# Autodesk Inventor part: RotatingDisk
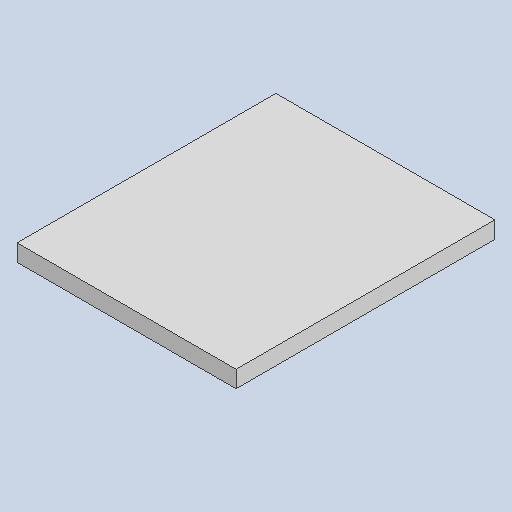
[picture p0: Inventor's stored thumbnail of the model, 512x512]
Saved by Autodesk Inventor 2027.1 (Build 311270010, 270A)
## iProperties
Created: 2026-07
Part Number: RotatingDisk
Material: Generic
Document SubType Name: Modeling
Designer: dunge
Density: 1 g/cm^3
Appearance: Default
Mass: 1.47303 g
Surface Area: 42.135 cm^2
Volume: 1.47303 cm^3
Author: dunge
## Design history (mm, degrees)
sketch "Sketch1"
  geometry: L1 (-0.381, 24.126)-(-0.381, 23.392); L2 (0.381, 24.126)-(0.381, 23.392); L3 (-2.901, 23.955)-(-2.824, 23.224); L4 (-2.143, 24.034)-(-2.066, 23.304); L5 (-5.389, 23.52)-(-5.236, 22.802); L6 (-4.644, 23.678)-(-4.491, 22.96); L7 (-7.818, 22.828)-(-7.591, 22.13); L8 (-7.093, 23.063)-(-6.866, 22.365); L9 (-10.161, 21.886)-(-9.862, 21.215); L10 (-9.465, 22.196)-(-9.166, 21.525); L11 (-12.393, 20.704)-(-12.026, 20.068); L12 (-11.733, 21.085)-(-11.366, 20.449); L13 (-14.489, 19.295)-(-14.058, 18.701); L14 (-13.873, 19.743)-(-13.441, 19.149); L15 (-16.427, 17.675)-(-15.935, 17.129); L16 (-15.861, 18.184)-(-15.369, 17.639); L17 (-18.184, 15.861)-(-17.639, 15.369); L18 (-17.675, 16.427)-(-17.129, 15.935); L19 (-19.743, 13.873)-(-19.149, 13.441); L20 (-19.295, 14.489)-(-18.701, 14.058); L21 (-21.085, 11.733)-(-20.449, 11.366); L22 (-20.704, 12.393)-(-20.068, 12.026); L23 (-22.196, 9.465)-(-21.525, 9.166); L24 (-21.886, 10.161)-(-21.215, 9.862); L25 (-23.063, 7.093)-(-22.365, 6.866); L26 (-22.828, 7.818)-(-22.13, 7.591); L27 (-23.678, 4.644)-(-22.96, 4.491); L28 (-23.52, 5.389)-(-22.802, 5.236); L29 (-24.034, 2.143)-(-23.304, 2.066); L30 (-23.955, 2.901)-(-23.224, 2.824); L31 (-24.126, -0.381)-(-23.392, -0.381); L32 (-24.126, 0.381)-(-23.392, 0.381); L33 (-23.955, -2.901)-(-23.224, -2.824); L34 (-24.034, -2.143)-(-23.304, -2.066); L35 (-23.52, -5.389)-(-22.802, -5.236); L36 (-23.678, -4.644)-(-22.96, -4.491); L37 (-22.828, -7.818)-(-22.13, -7.591); L38 (-23.063, -7.093)-(-22.365, -6.866); L39 (-21.886, -10.161)-(-21.215, -9.862); L40 (-22.196, -9.465)-(-21.525, -9.166); L41 (-20.704, -12.393)-(-20.068, -12.026); L42 (-21.085, -11.733)-(-20.449, -11.366); L43 (-19.295, -14.489)-(-18.701, -14.058); L44 (-19.743, -13.873)-(-19.149, -13.441); L45 (-17.675, -16.427)-(-17.129, -15.935); L46 (-18.184, -15.861)-(-17.639, -15.369); L47 (-15.861, -18.184)-(-15.369, -17.639); L48 (-16.427, -17.675)-(-15.935, -17.129); L49 (-13.873, -19.743)-(-13.441, -19.149); L50 (-14.489, -19.295)-(-14.058, -18.701); L51 (-11.733, -21.085)-(-11.366, -20.449); L52 (-12.393, -20.704)-(-12.026, -20.068); L53 (-9.465, -22.196)-(-9.166, -21.525); L54 (-10.161, -21.886)-(-9.862, -21.215); L55 (-7.093, -23.063)-(-6.866, -22.365); L56 (-7.818, -22.828)-(-7.591, -22.13); L57 (-4.644, -23.678)-(-4.491, -22.96); L58 (-5.389, -23.52)-(-5.236, -22.802); L59 (-2.143, -24.034)-(-2.066, -23.304); L60 (-2.901, -23.955)-(-2.824, -23.224); L61 (0.381, -24.126)-(0.381, -23.392); L62 (-0.381, -24.126)-(-0.381, -23.392); L63 (2.901, -23.955)-(2.824, -23.224); L64 (2.143, -24.034)-(2.066, -23.304)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; C1 r 25.4 at (0, 0); C2 r 2.842 at (0, 0); A1 r 0.381 centre (0, 23.392) between (-0.381, 23.392) and (0.381, 23.392); A2 r 0.381 centre (0, 24.126) between (0.381, 24.126) and (-0.381, 24.126); A3 r 0.381 centre (-2.445, 23.264) between (-2.824, 23.224) and (-2.066, 23.304); A4 r 0.381 centre (-2.522, 23.994) between (-2.143, 24.034) and (-2.901, 23.955); A5 r 0.381 centre (-4.864, 22.881) between (-5.236, 22.802) and (-4.491, 22.96); A6 r 0.381 centre (-5.016, 23.599) between (-4.644, 23.678) and (-5.389, 23.52); A7 r 0.381 centre (-7.229, 22.247) between (-7.591, 22.13) and (-6.866, 22.365); A8 r 0.381 centre (-7.455, 22.946) between (-7.093, 23.063) and (-7.818, 22.828); A9 r 0.381 centre (-9.514, 21.37) between (-9.862, 21.215) and (-9.166, 21.525); A10 r 0.381 centre (-9.813, 22.041) between (-9.465, 22.196) and (-10.161, 21.886); A11 r 0.381 centre (-11.696, 20.258) between (-12.026, 20.068) and (-11.366, 20.449); A12 r 0.381 centre (-12.063, 20.894) between (-11.733, 21.085) and (-12.393, 20.704); A13 r 0.381 centre (-13.75, 18.925) between (-14.058, 18.701) and (-13.441, 19.149); A14 r 0.381 centre (-14.181, 19.519) between (-13.873, 19.743) and (-14.489, 19.295); A15 r 0.381 centre (-15.652, 17.384) between (-15.935, 17.129) and (-15.369, 17.639); A16 r 0.381 centre (-16.144, 17.929) between (-15.861, 18.184) and (-16.427, 17.675); A17 r 0.381 centre (-17.384, 15.652) between (-17.639, 15.369) and (-17.129, 15.935); A18 r 0.381 centre (-17.929, 16.144) between (-17.675, 16.427) and (-18.184, 15.861); A19 r 0.381 centre (-18.925, 13.75) between (-19.149, 13.441) and (-18.701, 14.058); A20 r 0.381 centre (-19.519, 14.181) between (-19.295, 14.489) and (-19.743, 13.873); A21 r 0.381 centre (-20.258, 11.696) between (-20.449, 11.366) and (-20.068, 12.026); A22 r 0.381 centre (-20.894, 12.063) between (-20.704, 12.393) and (-21.085, 11.733); A23 r 0.381 centre (-21.37, 9.514) between (-21.525, 9.166) and (-21.215, 9.862); A24 r 0.381 centre (-22.041, 9.813) between (-21.886, 10.161) and (-22.196, 9.465); A25 r 0.381 centre (-22.247, 7.229) between (-22.365, 6.866) and (-22.13, 7.591); A26 r 0.381 centre (-22.946, 7.455) between (-22.828, 7.818) and (-23.063, 7.093); A27 r 0.381 centre (-22.881, 4.864) between (-22.96, 4.491) and (-22.802, 5.236); A28 r 0.381 centre (-23.599, 5.016) between (-23.52, 5.389) and (-23.678, 4.644); A29 r 0.381 centre (-23.264, 2.445) between (-23.304, 2.066) and (-23.224, 2.824); A30 r 0.381 centre (-23.994, 2.522) between (-23.955, 2.901) and (-24.034, 2.143); A31 r 0.381 centre (-23.392, 0) between (-23.392, -0.381) and (-23.392, 0.381); A32 r 0.381 centre (-24.126, 0) between (-24.126, 0.381) and (-24.126, -0.381); A33 r 0.381 centre (-23.264, -2.445) between (-23.224, -2.824) and (-23.304, -2.066); A34 r 0.381 centre (-23.994, -2.522) between (-24.034, -2.143) and (-23.955, -2.901); A35 r 0.381 centre (-22.881, -4.864) between (-22.802, -5.236) and (-22.96, -4.491); A36 r 0.381 centre (-23.599, -5.016) between (-23.678, -4.644) and (-23.52, -5.389); A37 r 0.381 centre (-22.247, -7.229) between (-22.13, -7.591) and (-22.365, -6.866); A38 r 0.381 centre (-22.946, -7.455) between (-23.063, -7.093) and (-22.828, -7.818); A39 r 0.381 centre (-21.37, -9.514) between (-21.215, -9.862) and (-21.525, -9.166); A40 r 0.381 centre (-22.041, -9.813) between (-22.196, -9.465) and (-21.886, -10.161); A41 r 0.381 centre (-20.258, -11.696) between (-20.068, -12.026) and (-20.449, -11.366); A42 r 0.381 centre (-20.894, -12.063) between (-21.085, -11.733) and (-20.704, -12.393); A43 r 0.381 centre (-18.925, -13.75) between (-18.701, -14.058) and (-19.149, -13.441); A44 r 0.381 centre (-19.519, -14.181) between (-19.743, -13.873) and (-19.295, -14.489); A45 r 0.381 centre (-17.384, -15.652) between (-17.129, -15.935) and (-17.639, -15.369); A46 r 0.381 centre (-17.929, -16.144) between (-18.184, -15.861) and (-17.675, -16.427); A47 r 0.381 centre (-15.652, -17.384) between (-15.369, -17.639) and (-15.935, -17.129); A48 r 0.381 centre (-16.144, -17.929) between (-16.427, -17.675) and (-15.861, -18.184); A49 r 0.381 centre (-13.75, -18.925) between (-13.441, -19.149) and (-14.058, -18.701); A50 r 0.381 centre (-14.181, -19.519) between (-14.489, -19.295) and (-13.873, -19.743); A51 r 0.381 centre (-11.696, -20.258) between (-11.366, -20.449) and (-12.026, -20.068); A52 r 0.381 centre (-12.063, -20.894) between (-12.393, -20.704) and (-11.733, -21.085); A53 r 0.381 centre (-9.514, -21.37) between (-9.166, -21.525) and (-9.862, -21.215); A54 r 0.381 centre (-9.813, -22.041) between (-10.161, -21.886) and (-9.465, -22.196); A55 r 0.381 centre (-7.229, -22.247) between (-6.866, -22.365) and (-7.591, -22.13); A56 r 0.381 centre (-7.455, -22.946) between (-7.818, -22.828) and (-7.093, -23.063); A57 r 0.381 centre (-4.864, -22.881) between (-4.491, -22.96) and (-5.236, -22.802); A58 r 0.381 centre (-5.016, -23.599) between (-5.389, -23.52) and (-4.644, -23.678); A59 r 0.381 centre (-2.445, -23.264) between (-2.066, -23.304) and (-2.824, -23.224); A60 r 0.381 centre (-2.522, -23.994) between (-2.901, -23.955) and (-2.143, -24.034); A61 r 0.381 centre (0, -23.392) between (0.381, -23.392) and (-0.381, -23.392); A62 r 0.381 centre (0, -24.126) between (-0.381, -24.126) and (0.381, -24.126); A63 r 0.381 centre (2.445, -23.264) between (2.824, -23.224) and (2.066, -23.304); A64 r 0.381 centre (2.522, -23.994) between (2.143, -24.034) and (2.901, -23.955)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; 3 further points; 2 other entities
  constraints: 242 end point, 240 point on circle, 122 centre point, 4 tangent, 2 coincident, 2 horizontal, 2 vertical, 1 symmetric about line, 605 other
  dimensions: "d0" = 50.8 diameter of C1; "d11" = 360 deg dimension on point (0, 0) L1.start (derived); "d15" = 0.3809 radius of A61; "d16" = 0.73432 distance of L62.start L62.end; "d17" = 24.1265 distance of C1.centre A62.centre
extrude "Extrusion1" new body sketch "Sketch1" distance "d5" = 1.524; taper "d6" = 0 deg
sketch "Sketch2"
  geometry: C1 r 2.842 at (0, 0); 1 further point
  constraints: 1 centre point, 1 coincident
extrude "Extrusion2" join sketch "Sketch2" distance "d7" = 1.524; taper "d8" = 0 deg; dims "d21" = 2.286, "d22" = 0
workplane "Work Plane1"
  workpoint "Work Point1"
sketch "Sketch4"
  geometry: L1 (0.381, -1.524)-(-0.381, -1.524) reference; L2 (0, -1.524)-(0, 0); L3 (0, 0)-(0, -1.524); L4 (0, -0.762)-(0.551, -1.313); L5 (0, -0.762)-(-0.594, -1.356)
  constraints: 8 end point, 2 midpoint, 1 collinear, 1 vertical
  dimensions: "d19" = 45 deg angle of L5 L3; "d20" = 45 deg angle of L4 L2
workpoint "Work Point2"
workaxis "Work Axis2"
workaxis "Work Axis3"
workplane "Work Plane2"
sketch "Sketch5"
  geometry: L1 (147.493, 189.054)-(-181.977, 189.054); L2 (-181.977, 189.054)-(-181.977, -200.318); L3 (-181.977, -200.318)-(147.493, -200.318); L4 (147.493, -200.318)-(147.493, 189.054); 1 further point
  constraints: 8 end point, 2 parallel, 1 horizontal, 1 perpendicular
extrude "Extrusion3" new body sketch "Sketch5" distance "d24" = 25.4; taper "d25" = 0 deg
body "Solid1"
node "Finishes"
node "Sketch Circular Pattern1" dims "d11" = 360 deg (derived)
workaxis "Work Axis1"
body "Solid2"
node "Finish1" dims "Finish1_Area" = 455.83638
node "Finish2" dims "Finish2_Area" = 12828.63257
other parameters: "d3" = 4.572, "d23" = 19.05
